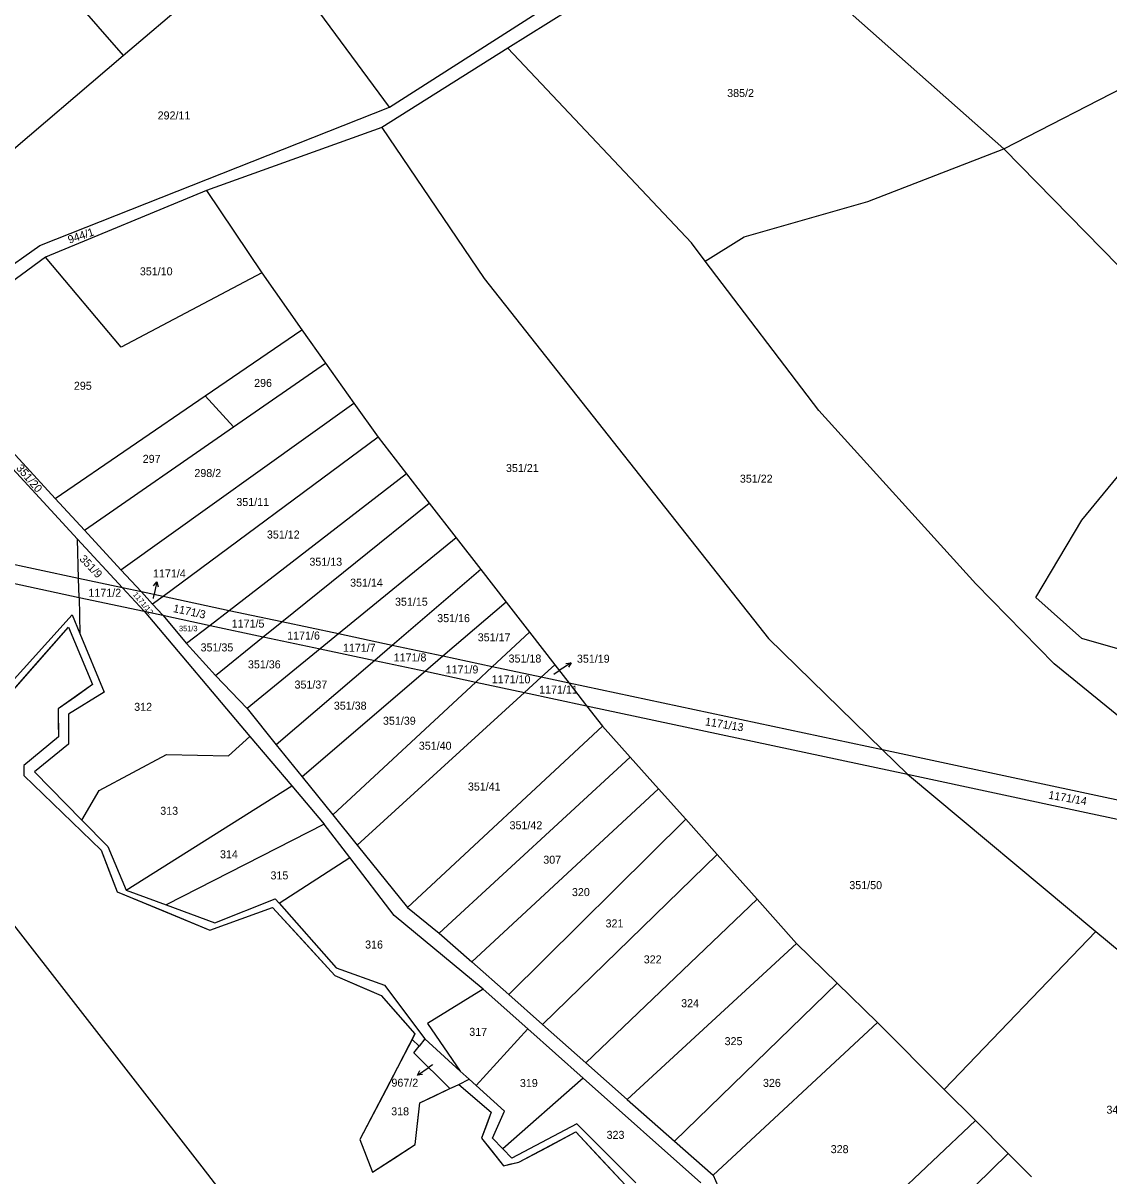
# Model space of a CAD drawing. Extents: x -593358 to -590116, y -1072518 to -1068420.
# Drawn here: x -592496.4 to -592265.8, y -1071586.8 to -1071341.9 of the extents above; entities that cross this region are included whole.
import ezdxf

# ---------------------------------------------------------------- set-up
doc = ezdxf.new("R2010")
doc.units = 0
for name, color, linetype in [('katastrální hranice', 7, 'Continuous'), ('Obvod s Petrovicemi', 7, 'Continuous'), ('Parcela KN', 7, 'Continuous'), ('Parcela ZE', 7, 'Continuous'), ('Parcelní číslo', 7, 'Continuous'), ('vnější obvod_šetřený', 7, 'Continuous'), ('Vrstva 16', 7, 'Continuous')]:
    doc.layers.add(name, color=color, linetype=linetype)

msp = doc.modelspace()

# ---------------------------------------------------------------- linework, layer by layer
at = {"layer": 'katastrální hranice'}
for p, q in [((-592501.48, -1071486.92), (-592486.77, -1071470.26)), ((-592486.77, -1071470.26), (-592481.65, -1071482.43)), ((-592481.65, -1071482.43), (-592489, -1071487.6)), ((-592489, -1071487.6), (-592488.93, -1071493.5)), ((-592488.93, -1071493.5), (-592496.27, -1071499.6)), ((-592496.27, -1071499.6), (-592496.28, -1071501.73)), ((-592496.28, -1071501.73), (-592479.84, -1071517.63)), ((-592479.84, -1071517.63), (-592476.45, -1071526.46)), ((-592476.45, -1071526.46), (-592456.78, -1071534.58)), ((-592456.78, -1071534.58), (-592443.42, -1071529.76)), ((-592443.42, -1071529.76), (-592430.19, -1071544.21)), ((-592430.19, -1071544.21), (-592420.39, -1071548.47)), ((-592420.39, -1071548.47), (-592413.2, -1071556.64)), ((-592413.2, -1071556.64), (-592413.81, -1071557.81)), ((-592413.81, -1071557.81), (-592424.86, -1071579.06)), ((-592405.75, -1071568.27), (-592403.86, -1071567.38)), ((-592403.86, -1071567.38), (-592396.97, -1071573.3)), ((-592412.12, -1071571.29), (-592405.75, -1071568.27)), ((-592413.13, -1071580.15), (-592412.12, -1071571.29)), ((-592396.97, -1071573.3), (-592399.03, -1071578.82)), ((-592424.86, -1071579.06), (-592422.19, -1071586.05)), ((-592399.03, -1071578.82), (-592394.36, -1071584.66)), ((-592391.09, -1071583.91), (-592379.03, -1071577.46)), ((-592379.03, -1071577.46), (-592368.46, -1071588.76)), ((-592422.19, -1071586.05), (-592413.13, -1071580.15)), ((-592394.36, -1071584.66), (-592391.09, -1071583.91))]:
    msp.add_line(p, q, dxfattribs=at)
at = {"layer": 'Obvod s Petrovicemi'}
for p, q in [((-592458.415, -1071584.865), (-592498.9, -1071532.82)), ((-592417.93, -1071636.91), (-592458.415, -1071584.865))]:
    msp.add_line(p, q, dxfattribs=at)
at = {"layer": 'Parcela KN'}
for p, q in [((-592345.86, -1071317.37), (-592393.45, -1071347.23)), ((-592418.62, -1071359.76), (-592382.34, -1071336.5)), ((-592393.45, -1071347.23), (-592420.25, -1071364.05)), ((-592492.89, -1071389.1), (-592418.62, -1071359.76)), ((-592420.25, -1071364.05), (-592457.47, -1071377.44)), ((-592457.47, -1071377.44), (-592491.65, -1071391.61)), ((-592504.16, -1071397.12), (-592492.89, -1071389.1)), ((-592491.65, -1071391.61), (-592502.36, -1071399.46)), ((-592484.63, -1071459.91), (-592532.66, -1071449.67)), ((-592534.44, -1071453.24), (-592484.51, -1071463.9)), ((-592475.28, -1071461.9), (-592484.63, -1071459.91)), ((-592471.3, -1071462.75), (-592475.28, -1071461.9)), ((-592484.51, -1071463.9), (-592484.38, -1071471.55)), ((-592484.51, -1071463.9), (-592470.73, -1071466.84)), ((-592466.7, -1071463.73), (-592471.3, -1071462.75)), ((-592452.63, -1071466.73), (-592466.7, -1071463.73)), ((-592470.73, -1071466.84), (-592448.23, -1071493.44)), ((-592470.73, -1071466.84), (-592466.75, -1071467.69)), ((-592441.49, -1071469.1), (-592452.63, -1071466.73)), ((-592501.56, -1071484.85), (-592486.01, -1071467.59)), ((-592486.01, -1071467.59), (-592484.38, -1071471.55)), ((-592466.75, -1071467.69), (-592456.66, -1071469.84)), ((-592429.45, -1071471.67), (-592441.49, -1071469.1)), ((-592484.38, -1071471.55), (-592479.23, -1071484.05)), ((-592456.66, -1071469.84), (-592445.4, -1071472.25)), ((-592418, -1071474.11), (-592429.45, -1071471.67)), ((-592445.4, -1071472.25), (-592433.31, -1071474.83)), ((-592407.23, -1071476.41), (-592418, -1071474.11)), ((-592433.31, -1071474.83), (-592421.73, -1071477.3)), ((-592396.77, -1071478.64), (-592407.23, -1071476.41)), ((-592421.73, -1071477.3), (-592410.96, -1071479.6)), ((-592386.4, -1071480.85), (-592396.77, -1071478.64)), ((-592410.96, -1071479.6), (-592400.27, -1071481.89)), ((-592380.46, -1071482.12), (-592386.4, -1071480.85)), ((-592479.23, -1071484.05), (-592486.8, -1071488.73)), ((-592400.27, -1071481.89), (-592389.95, -1071484.1)), ((-592389.95, -1071484.1), (-592376.73, -1071486.92)), ((-592313.86, -1071496.32), (-592380.46, -1071482.12)), ((-592486.8, -1071488.73), (-592486.8, -1071495.12)), ((-592376.73, -1071486.92), (-592308.58, -1071501.48)), ((-592452.8, -1071497.56), (-592448.23, -1071493.44)), ((-592448.23, -1071493.44), (-592439.34, -1071503.95)), ((-592486.8, -1071495.12), (-592493.98, -1071501)), ((-592300.36, -1071499.2), (-592313.86, -1071496.32)), ((-592480.25, -1071504.95), (-592465.99, -1071497.3)), ((-592465.99, -1071497.3), (-592452.8, -1071497.56)), ((-592493.98, -1071501), (-592483.93, -1071511.24)), ((-592234.13, -1071513.33), (-592300.36, -1071499.2)), ((-592308.58, -1071501.48), (-592270.64, -1071509.59)), ((-592483.93, -1071511.24), (-592480.25, -1071504.95)), ((-592474.54, -1071526.12), (-592439.34, -1071503.95)), ((-592439.34, -1071503.95), (-592432.49, -1071512.05)), ((-592270.64, -1071509.59), (-592227.41, -1071518.82)), ((-592483.93, -1071511.24), (-592478.44, -1071516.83)), ((-592432.49, -1071512.05), (-592466.05, -1071529.25)), ((-592478.44, -1071516.83), (-592474.54, -1071526.12)), ((-592474.54, -1071526.12), (-592466.05, -1071529.25)), ((-592455.72, -1071533.06), (-592442.86, -1071527.98)), ((-592442.86, -1071527.98), (-592442.06, -1071528.88)), ((-592466.05, -1071529.25), (-592455.72, -1071533.06)), ((-592442.06, -1071528.88), (-592429.93, -1071542.62)), ((-592429.93, -1071542.62), (-592419.67, -1071546.31)), ((-592419.67, -1071546.31), (-592411.1, -1071557.71)), ((-592411.1, -1071557.71), (-592412.29, -1071559.28)), ((-592411.1, -1071557.71), (-592403.55, -1071564.57)), ((-592412.29, -1071559.28), (-592413.81, -1071557.81)), ((-592413.41, -1071560.69), (-592412.29, -1071559.28)), ((-592405.75, -1071568.27), (-592413.41, -1071560.69)), ((-592403.55, -1071564.57), (-592401.66, -1071566.29)), ((-592403.86, -1071567.38), (-592401.66, -1071566.29)), ((-592401.66, -1071566.29), (-592400.19, -1071567.62)), ((-592400.19, -1071567.62), (-592394.16, -1071573.1)), ((-592396.74, -1071578.8), (-592394.16, -1071573.1)), ((-592378.82, -1071575.78), (-592392.58, -1071583.04)), ((-592366.28, -1071588.32), (-592378.82, -1071575.78)), ((-592394.51, -1071581.08), (-592396.74, -1071578.8)), ((-592392.58, -1071583.04), (-592394.51, -1071581.08))]:
    msp.add_line(p, q, dxfattribs=at)
at = {"layer": 'Parcela ZE'}
for p, q in [((-592345.86, -1071317.37), (-592288.09, -1071368.59)), ((-592475.14, -1071348.74), (-592445.38, -1071323.35)), ((-592418.62, -1071359.76), (-592445.38, -1071323.35)), ((-592494.16, -1071327.04), (-592475.14, -1071348.74)), ((-592515.68, -1071383.33), (-592475.14, -1071348.74)), ((-592354.48, -1071388.59), (-592393.45, -1071347.23)), ((-592288.09, -1071368.59), (-592251.4, -1071349.73)), ((-592420.25, -1071364.05), (-592398.46, -1071396.11)), ((-592317, -1071379.81), (-592288.09, -1071368.59)), ((-592288.09, -1071368.59), (-592213.83, -1071444.58)), ((-592457.47, -1071377.44), (-592445.68, -1071394.94)), ((-592343.26, -1071387.31), (-592317, -1071379.81)), ((-592351.56, -1071392.43), (-592354.48, -1071388.59)), ((-592351.56, -1071392.43), (-592343.26, -1071387.31)), ((-592475.58, -1071410.75), (-592491.65, -1071391.61)), ((-592327.41, -1071424.19), (-592351.56, -1071392.43)), ((-592445.68, -1071394.94), (-592475.58, -1071410.75)), ((-592445.68, -1071394.94), (-592437.18, -1071407.03)), ((-592398.46, -1071396.11), (-592338.1, -1071472.63)), ((-592457.74, -1071421.09), (-592437.18, -1071407.03)), ((-592437.18, -1071407.03), (-592432.19, -1071414.11)), ((-592515.3, -1071414.97), (-592489.59, -1071442.88)), ((-592451.71, -1071427.63), (-592432.19, -1071414.11)), ((-592432.19, -1071414.11), (-592426.2, -1071422.62)), ((-592516.86, -1071416.84), (-592484.88, -1071451.5)), ((-592489.59, -1071442.88), (-592457.74, -1071421.09)), ((-592475.64, -1071458.04), (-592426.2, -1071422.62)), ((-592457.74, -1071421.09), (-592451.71, -1071427.63)), ((-592426.2, -1071422.62), (-592421.02, -1071429.89)), ((-592294.08, -1071461.01), (-592327.41, -1071424.19)), ((-592483.41, -1071449.59), (-592451.71, -1071427.63)), ((-592421.02, -1071429.89), (-592466.7, -1071463.73)), ((-592421.02, -1071429.89), (-592414.98, -1071437.67)), ((-592271.56, -1071447.46), (-592261.35, -1071435.07)), ((-592414.98, -1071437.67), (-592452.63, -1071466.73)), ((-592414.98, -1071437.67), (-592410.15, -1071443.89)), ((-592489.59, -1071442.88), (-592483.41, -1071449.59)), ((-592441.49, -1071469.1), (-592410.15, -1071443.89)), ((-592410.15, -1071443.89), (-592404.46, -1071451.21)), ((-592281.32, -1071463.9), (-592271.56, -1071447.46)), ((-592483.41, -1071449.59), (-592475.64, -1071458.04)), ((-592484.88, -1071451.5), (-592475.28, -1071461.9)), ((-592484.63, -1071459.91), (-592484.88, -1071451.5)), ((-592404.46, -1071451.21), (-592429.45, -1071471.67)), ((-592404.46, -1071451.21), (-592399.19, -1071458)), ((-592475.64, -1071458.04), (-592471.3, -1071462.75)), ((-592399.19, -1071458), (-592418, -1071474.11)), ((-592399.19, -1071458), (-592393.82, -1071464.92)), ((-592484.51, -1071463.9), (-592484.63, -1071459.91)), ((-592475.28, -1071461.9), (-592470.73, -1071466.84)), ((-592277.39, -1071478), (-592294.08, -1071461.01)), ((-592471.3, -1071462.75), (-592468.9, -1071465.36)), ((-592466.7, -1071463.73), (-592468.9, -1071465.36)), ((-592271.56, -1071472.61), (-592281.32, -1071463.9)), ((-592468.9, -1071465.36), (-592466.75, -1071467.69)), ((-592452.63, -1071466.73), (-592456.66, -1071469.84)), ((-592393.82, -1071464.92), (-592407.23, -1071476.41)), ((-592393.82, -1071464.92), (-592388.86, -1071471.3)), ((-592466.75, -1071467.69), (-592461.7, -1071473.71)), ((-592445.4, -1071472.25), (-592441.49, -1071469.1)), ((-592456.66, -1071469.84), (-592461.7, -1071473.71)), ((-592429.45, -1071471.67), (-592433.31, -1071474.83)), ((-592396.77, -1071478.64), (-592388.86, -1071471.3)), ((-592388.86, -1071471.3), (-592383.5, -1071478.2)), ((-592461.7, -1071473.71), (-592455.58, -1071480.5)), ((-592455.58, -1071480.5), (-592445.4, -1071472.25)), ((-592418, -1071474.11), (-592421.73, -1071477.3)), ((-592338.1, -1071472.63), (-592313.86, -1071496.32)), ((-592261.42, -1071475.54), (-592271.56, -1071472.61)), ((-592433.31, -1071474.83), (-592448.82, -1071487.53)), ((-592407.23, -1071476.41), (-592410.96, -1071479.6)), ((-592421.73, -1071477.3), (-592442.64, -1071495.21)), ((-592400.27, -1071481.89), (-592396.77, -1071478.64)), ((-592383.5, -1071478.2), (-592386.4, -1071480.85)), ((-592383.5, -1071478.2), (-592380.46, -1071482.12)), ((-592234.13, -1071513.33), (-592277.39, -1071478)), ((-592455.58, -1071480.5), (-592448.82, -1071487.53)), ((-592410.96, -1071479.6), (-592437.15, -1071502.03)), ((-592386.4, -1071480.85), (-592389.95, -1071484.1)), ((-592430.65, -1071510.1), (-592400.27, -1071481.89)), ((-592389.95, -1071484.1), (-592425.44, -1071516.57)), ((-592380.46, -1071482.12), (-592376.73, -1071486.92)), ((-592448.82, -1071487.53), (-592442.64, -1071495.21)), ((-592376.73, -1071486.92), (-592373.34, -1071491.29)), ((-592414.78, -1071529.81), (-592373.34, -1071491.29)), ((-592373.34, -1071491.29), (-592367.5, -1071497.83)), ((-592442.64, -1071495.21), (-592437.15, -1071502.03)), ((-592313.86, -1071496.32), (-592308.58, -1071501.48)), ((-592367.5, -1071497.83), (-592408.02, -1071535.24)), ((-592367.5, -1071497.83), (-592361.48, -1071504.56)), ((-592437.15, -1071502.03), (-592430.65, -1071510.1)), ((-592308.58, -1071501.48), (-592268.57, -1071534.86)), ((-592401.13, -1071541.33), (-592361.48, -1071504.56)), ((-592361.48, -1071504.56), (-592355.68, -1071511.05)), ((-592430.65, -1071510.1), (-592425.44, -1071516.57)), ((-592393.24, -1071548.3), (-592355.68, -1071511.05)), ((-592355.68, -1071511.05), (-592349, -1071518.53)), ((-592427.02, -1071519.19), (-592432.49, -1071512.05)), ((-592425.44, -1071516.57), (-592414.78, -1071529.81)), ((-592386.08, -1071554.64), (-592349, -1071518.53)), ((-592349, -1071518.53), (-592340.52, -1071528.02)), ((-592442.06, -1071528.88), (-592427.02, -1071519.19)), ((-592417.61, -1071531.46), (-592427.02, -1071519.19)), ((-592376.89, -1071562.77), (-592340.52, -1071528.02)), ((-592340.52, -1071528.02), (-592332.13, -1071537.44)), ((-592414.78, -1071529.81), (-592408.02, -1071535.24)), ((-592398.71, -1071547.13), (-592417.61, -1071531.46)), ((-592408.02, -1071535.24), (-592401.13, -1071541.33)), ((-592300.75, -1071568.45), (-592268.57, -1071534.86)), ((-592268.57, -1071534.86), (-592221.13, -1071574.43)), ((-592368.08, -1071570.56), (-592332.13, -1071537.44)), ((-592332.13, -1071537.44), (-592323.51, -1071545.86)), ((-592401.13, -1071541.33), (-592393.24, -1071548.3)), ((-592398.71, -1071547.13), (-592410.55, -1071554.47)), ((-592389.23, -1071555.56), (-592398.71, -1071547.13)), ((-592358.03, -1071579.45), (-592323.51, -1071545.86)), ((-592323.51, -1071545.86), (-592314.92, -1071554.26)), ((-592393.24, -1071548.3), (-592386.08, -1071554.64)), ((-592410.55, -1071554.47), (-592403.55, -1071564.57)), ((-592386.08, -1071554.64), (-592376.89, -1071562.77)), ((-592349.87, -1071586.67), (-592314.92, -1071554.26)), ((-592314.92, -1071554.26), (-592300.75, -1071568.45)), ((-592389.23, -1071555.56), (-592400.19, -1071567.62)), ((-592377.46, -1071566.03), (-592389.23, -1071555.56)), ((-592376.89, -1071562.77), (-592368.08, -1071570.56)), ((-592377.46, -1071566.03), (-592394.51, -1071581.08)), ((-592352.44, -1071588.27), (-592377.46, -1071566.03)), ((-592300.75, -1071568.45), (-592294.15, -1071575.07)), ((-592368.08, -1071570.56), (-592358.03, -1071579.45)), ((-592336.91, -1071615.48), (-592294.15, -1071575.07)), ((-592294.15, -1071575.07), (-592287.18, -1071582.04)), ((-592358.03, -1071579.45), (-592349.87, -1071586.67)), ((-592332.14, -1071626.07), (-592287.18, -1071582.04)), ((-592287.18, -1071582.04), (-592282.23, -1071586.99)), ((-592349.87, -1071586.67), (-592336.91, -1071615.48))]:
    msp.add_line(p, q, dxfattribs=at)
at = {"layer": 'vnější obvod_šetřený'}
msp.add_lwpolyline([(-592501.48, -1071486.92), (-592494.125, -1071478.59), (-592486.77, -1071470.26), (-592484.21, -1071476.345), (-592481.65, -1071482.43), (-592485.325, -1071485.015), (-592489, -1071487.6), (-592488.965, -1071490.55), (-592488.93, -1071493.5), (-592492.6, -1071496.55), (-592496.27, -1071499.6), (-592496.275, -1071500.665), (-592496.28, -1071501.73), (-592488.06, -1071509.68), (-592479.84, -1071517.63), (-592478.145, -1071522.045), (-592476.45, -1071526.46), (-592466.615, -1071530.52), (-592456.78, -1071534.58), (-592450.1, -1071532.17), (-592443.42, -1071529.76), (-592436.805, -1071536.985), (-592430.19, -1071544.21), (-592425.29, -1071546.34), (-592420.39, -1071548.47), (-592416.795, -1071552.555), (-592413.2, -1071556.64), (-592419.335, -1071568.435), (-592424.86, -1071579.06), (-592423.525, -1071582.555), (-592422.19, -1071586.05), (-592417.66, -1071583.1), (-592413.13, -1071580.15), (-592412.625, -1071575.72), (-592412.12, -1071571.29), (-592408.935, -1071569.78), (-592405.75, -1071568.27), (-592404.805, -1071567.825), (-592403.86, -1071567.38), (-592400.415, -1071570.34), (-592396.97, -1071573.3), (-592398, -1071576.06), (-592399.03, -1071578.82), (-592396.695, -1071581.74), (-592394.36, -1071584.66), (-592392.725, -1071584.285), (-592391.09, -1071583.91), (-592385.06, -1071580.685), (-592379.03, -1071577.46), (-592373.745, -1071583.11), (-592368.46, -1071588.76)], dxfattribs=at)
at = {"layer": 'Vrstva 16'}
for p, q in [((-592468.026, -1071460.559), (-592468.62, -1071463.5)), ((-592468.75, -1071464.12), (-592468.62, -1071463.5)), ((-592380.018, -1071477.784), (-592382.52, -1071479.44)), ((-592383.66, -1071480.19), (-592382.52, -1071479.44)), ((-592412.676, -1071565.385), (-592410.18, -1071563.72)), ((-592409.44, -1071563.22), (-592410.18, -1071563.72))]:
    msp.add_line(p, q, dxfattribs=at)
for points in [[(-592468.714, -1071461.441), (-592468.026, -1071460.559), (-592467.734, -1071461.638)], [(-592381.128, -1071477.919), (-592380.018, -1071477.784), (-592380.576, -1071478.753)], [(-592411.566, -1071565.246), (-592412.676, -1071565.385), (-592412.121, -1071564.414)]]:
    msp.add_lwpolyline(points, dxfattribs=at)

# ---------------------------------------------------------------- texts
at = {"layer": 'Parcelní číslo'}
for s, height, p in [('385/2', 1.7, (-592346.867, -1071357.58)), ('292/11', 1.7, (-592467.844, -1071362.34)), ('351/10', 1.7, (-592471.617, -1071395.47)), ('295', 1.7, (-592485.635, -1071419.78)), ('296', 1.7, (-592447.348, -1071419.18)), ('297', 1.7, (-592471.008, -1071435.31)), ('298/2', 1.7, (-592460.037, -1071438.33)), ('351/21', 1.7, (-592393.854, -1071437.26)), ('351/22', 1.7, (-592344.166, -1071439.52)), ('351/11', 1.7, (-592451.122, -1071444.48)), ('351/12', 1.7, (-592444.634, -1071451.39)), ('351/13', 1.7, (-592435.607, -1071457.17)), ('1171/2', 1.7, (-592482.542, -1071463.76)), ('351/14', 1.7, (-592426.96, -1071461.62)), ('1171/4', 0.1, (-592468.929, -1071464.1)), ('351/15', 1.7, (-592417.427, -1071465.67)), ('1171/5', 1.7, (-592452.115, -1071470.32)), ('351/16', 1.7, (-592408.46, -1071469.16)), ('351/3', 1.14, (-592463.307, -1071471.08)), ('1171/6', 1.7, (-592440.328, -1071472.86)), ('351/17', 1.7, (-592399.85, -1071473.23)), ('351/35', 1.7, (-592458.722, -1071475.38)), ('1171/7', 1.7, (-592428.488, -1071475.46)), ('1171/8', 1.7, (-592417.708, -1071477.51)), ('351/18', 1.7, (-592393.3, -1071477.74)), ('351/36', 1.7, (-592448.665, -1071478.98)), ('1171/9', 1.7, (-592406.668, -1071480.06)), ('351/37', 1.7, (-592438.765, -1071483.27)), ('1171/10', 1.7, (-592396.876, -1071482.16)), ('351/19', 0.1, (-592383.839, -1071480.19)), ('1171/11', 1.7, (-592386.811, -1071484.34)), ('312', 1.7, (-592472.827, -1071488)), ('351/38', 1.7, (-592430.416, -1071487.75)), ('351/39', 1.7, (-592419.975, -1071490.96)), ('351/40', 1.7, (-592412.365, -1071496.27)), ('351/41', 1.7, (-592401.94, -1071504.94)), ('313', 1.7, (-592467.29, -1071510.09)), ('351/42', 1.7, (-592393.092, -1071513.17)), ('314', 1.7, (-592454.603, -1071519.33)), ('307', 1.7, (-592385.928, -1071520.49)), ('315', 1.7, (-592443.87, -1071523.82)), ('320', 1.7, (-592379.842, -1071527.37)), ('351/50', 1.7, (-592320.922, -1071525.89)), ('321', 1.7, (-592372.697, -1071534.02)), ('316', 1.7, (-592423.773, -1071538.51)), ('322', 1.7, (-592364.589, -1071541.67)), ('324', 1.7, (-592356.645, -1071550.98)), ('317', 1.7, (-592401.653, -1071557.06)), ('325', 1.7, (-592347.412, -1071559.04)), ('967/2', 0.1, (-592409.644, -1071563.22)), ('319', 1.7, (-592390.893, -1071567.94)), ('326', 1.7, (-592339.265, -1071567.91)), ('318', 1.7, (-592418.233, -1071573.95)), ('347/4', 1.7, (-592266.31, -1071573.61)), ('323', 1.7, (-592372.482, -1071578.95)), ('328', 1.7, (-592324.875, -1071581.99))]:
    msp.add_text(s, height=height, dxfattribs=at).set_placement(p)
for s, height, rotation, p in [('944/1', 1.7, 18.67843, (-592486.583, -1071388.758)), ('351/20', 1.7, 310.65772, (-592498.002, -1071436.499)), ('351/9', 1.7, 313.6371, (-592484.581, -1071455.85)), ('1171/12', 1.14, 309.45451, (-592473.161, -1071463.322)), ('1171/3', 1.7, 348.07186, (-592464.658, -1071466.994)), ('1171/13', 1.7, 350.70747, (-592351.651, -1071491.06)), ('1171/14', 1.7, 349.96262, (-592278.728, -1071506.641))]:
    msp.add_text(s, height=height, rotation=rotation, dxfattribs=at).set_placement(p)
at = {"layer": 'Vrstva 16'}
for s, p in [('1171/4', (-592468.827, -1071459.67)), ('351/19', (-592378.783, -1071477.78)), ('967/2', (-592418.181, -1071567.87))]:
    msp.add_text(s, height=1.7, dxfattribs=at).set_placement(p)

doc.saveas('drawing.dxf')
